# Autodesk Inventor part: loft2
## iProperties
Author: Administrator
Created: 2000-12
Part Number: loft2
Document SubType Name: Modeling
Designer: Administrator
Control State: 0
Master: False
Checked Out: False
PropertySet Name: Design Tracking Control
Shininess: 0.0
PropertySet Name: _Private Model Information
Density: 0.0
Volumn: 0.0
Area: 0.0
PropertySet Name: Model Information
